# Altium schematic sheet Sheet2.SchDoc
size B; SheetNumber: 2; SheetTotal: 2
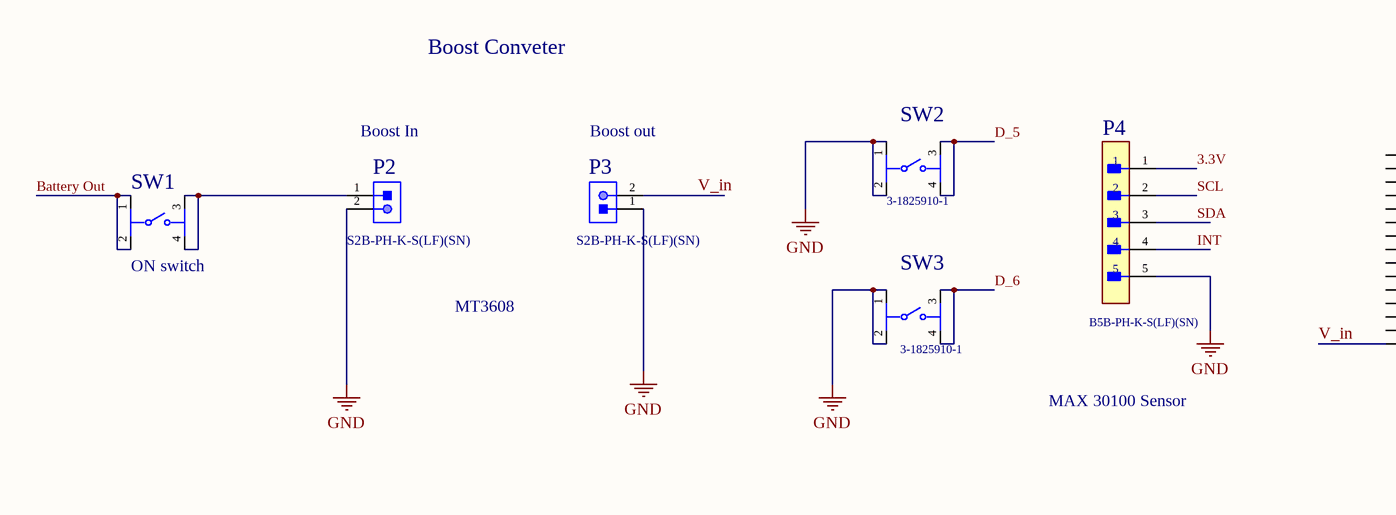
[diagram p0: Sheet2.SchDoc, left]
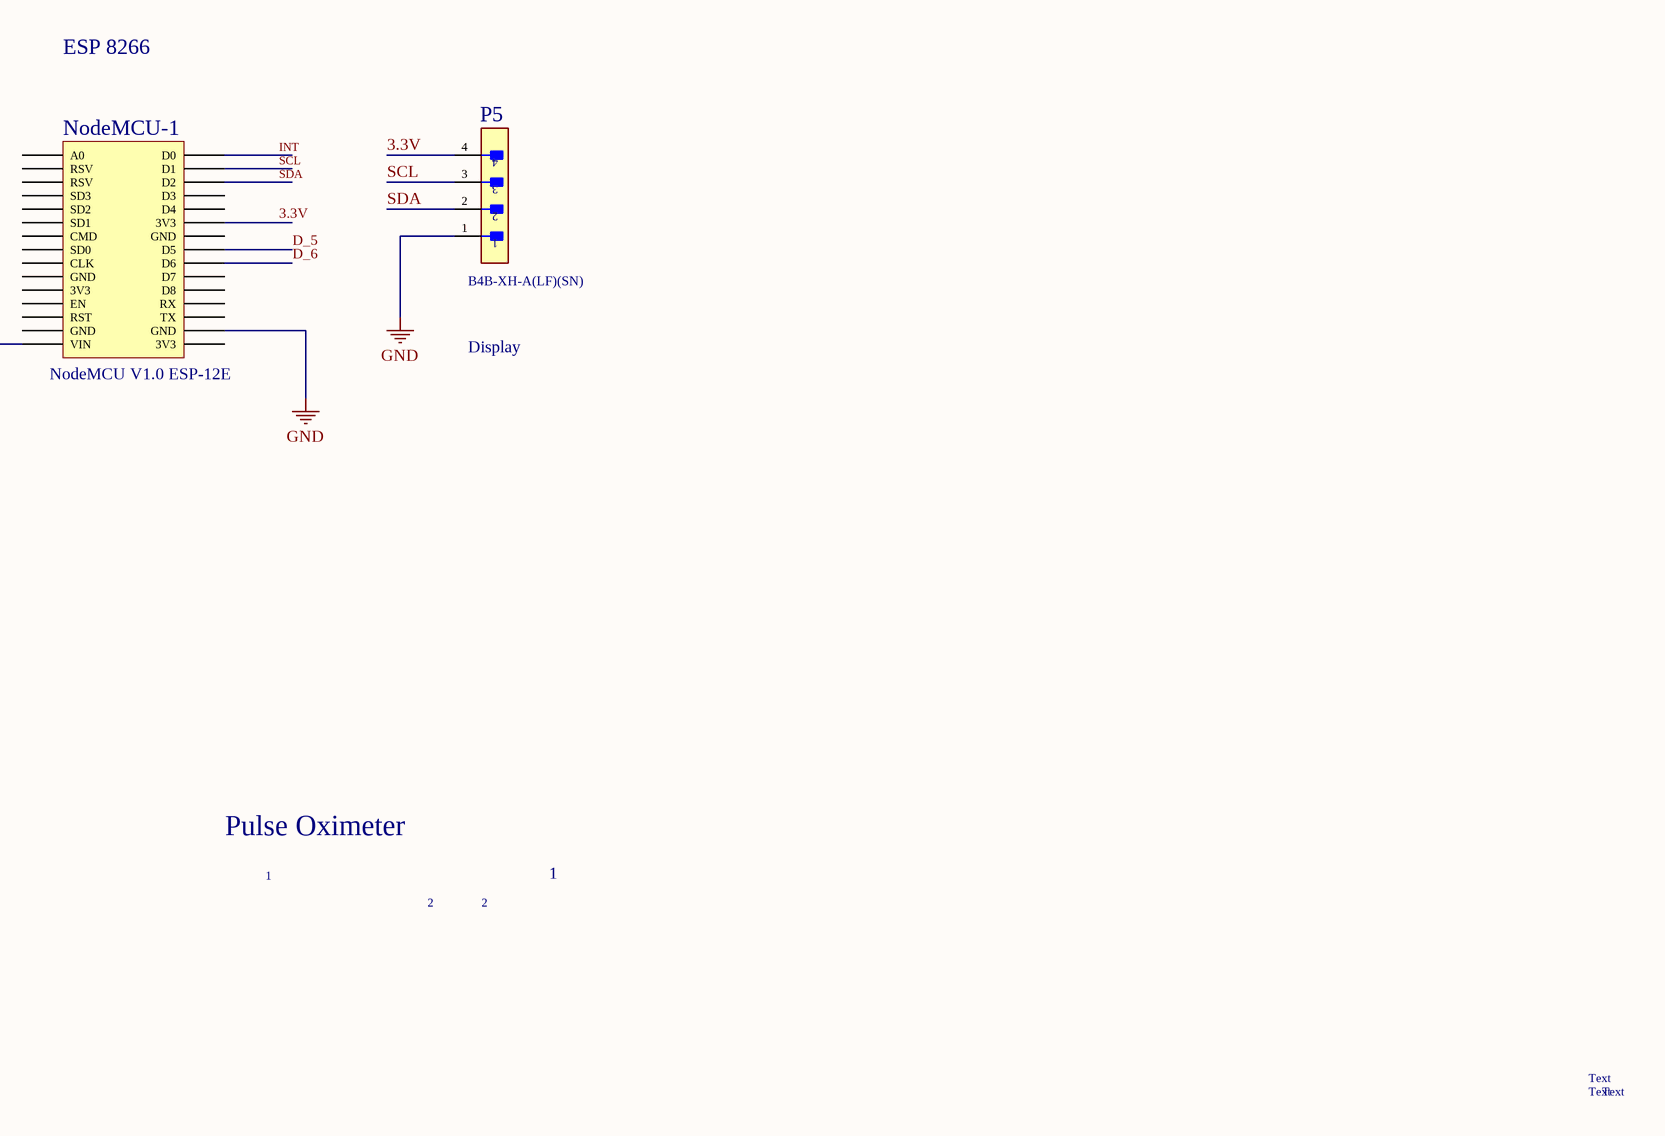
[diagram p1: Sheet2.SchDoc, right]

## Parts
NodeMCU-1  NodeMCU V1.0 ESP-12E  [NodeMCU V1.0 ESP-12E]
P2  S2B-PH-K-S(LF)(SN)  [JST-S2B-PH-K-S_V]
P3  S2B-PH-K-S(LF)(SN)  [JST-S2B-PH-K-S_V]
P4  B5B-PH-K-S(LF)(SN)  [FP-B5B-PH-K-S_LF_SN-MFG]
P5  B4B-XH-A(LF)(SN)  [FP-B4B-XH-A_LF_SN-MFG]
SW1  ON switch  [FP-3-1825910-1-MFG]
SW2  3-1825910-1  [FP-3-1825910-1-MFG]
SW3  3-1825910-1  [FP-3-1825910-1-MFG]

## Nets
GND: NodeMCU-1.GND P2.2 P3.1 P4.5 P5.1 SW2.1 SW2.2 SW3.1 SW3.2
3.3V: NodeMCU-1.3V3 P4.1 P5.4
Battery Out: SW1.1 SW1.2
D_5: NodeMCU-1.D5 SW2.3 SW2.4
D_6: NodeMCU-1.D6 SW3.3 SW3.4
INT: NodeMCU-1.D0 P4.4
SCL: NodeMCU-1.D1 P4.2 P5.3
SDA: NodeMCU-1.D2 P4.3 P5.2
V_in: NodeMCU-1.VIN P3.2
NetP2_1: P2.1 SW1.3 SW1.4

Not connected (* = marked no-connect by the designer): NodeMCU-1 A0 CLK CMD D3 D4 D7 D8 EN RST RSV RX SD0 SD1 SD2 SD3 TX

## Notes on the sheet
- Boost Conveter
- ESP 8266
- Boost In
- Boost out
- MT3608
- Display
- MAX 30100 Sensor
- Pulse Oximeter
- 1
- 2
- Text

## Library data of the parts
NodeMCU-1 = NodeMCU V1.0 ESP-12E: NodeMCU V1.0 ESP8266 (ESP-12E)
P2 P3 = CMP-1755-00004-1: Male Header, Pitch 2 mm, 1 x 2 Position, Height 4.8 mm, Tail Length 3.4 mm, -25 to 85 degC, RoHS, Bulk; Case\Package: Radial; Tolerance: 20%; Capacitance: 10 uF; Voltage Rating (DC): 50 V
P4 = CMP-2000-05908-2: CONN HEADER VERT 5POS 2MM; Voltage Rating (AC): 100V; Number of Positions: 5; Contact Resistance: 20mR; Insulation Resistance: 1MR; Current Rating: 2A; Gender: Male; Mated Stacking Heights: 8mm
P5 = CMP-17439-000250-1: CONN HEADER VERT 4POS 2.5MM; Number of Contacts: 4; Contact Resistance: 20mR; Voltage Rating: 250V; Max Current Rating: 3A; Gender: Male; Wire/Cable Gauge: 22AWG; Mated Stacking Heights: 9.8mm; Insulation Resistance: 1GR
SW1 = CMP-03407-000001-1: SWITCH TACTILE SPST-NO 0.05A 24V; Manufacturer: TE Connectivity; Manufacturer Part Number: 3-1825910-1; Operating Force: 160gf; Contact Current Rating: 50mA; Contact Resistance: 100mΩ; Electromechanical Life: 100000Cycles
SW2 SW3 = CMP-03407-000001-1: SWITCH TACTILE SPST-NO 0.05A 24V; Manufacturer: TE Connectivity; Operating Force: 160gf; Contact Current Rating: 50mA; Contact Resistance: 100mΩ; Electromechanical Life: 100000Cycles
